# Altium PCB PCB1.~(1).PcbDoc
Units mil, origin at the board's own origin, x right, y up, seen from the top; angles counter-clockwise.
Board outline 2756 x 2756 mil, 4 copper layers (Top Layer, Internal Plane 1, Internal Plane 2, Bottom Layer), stack 18.2 mil thick; 14 components, 0 nets, 59 pads, 0 vias.
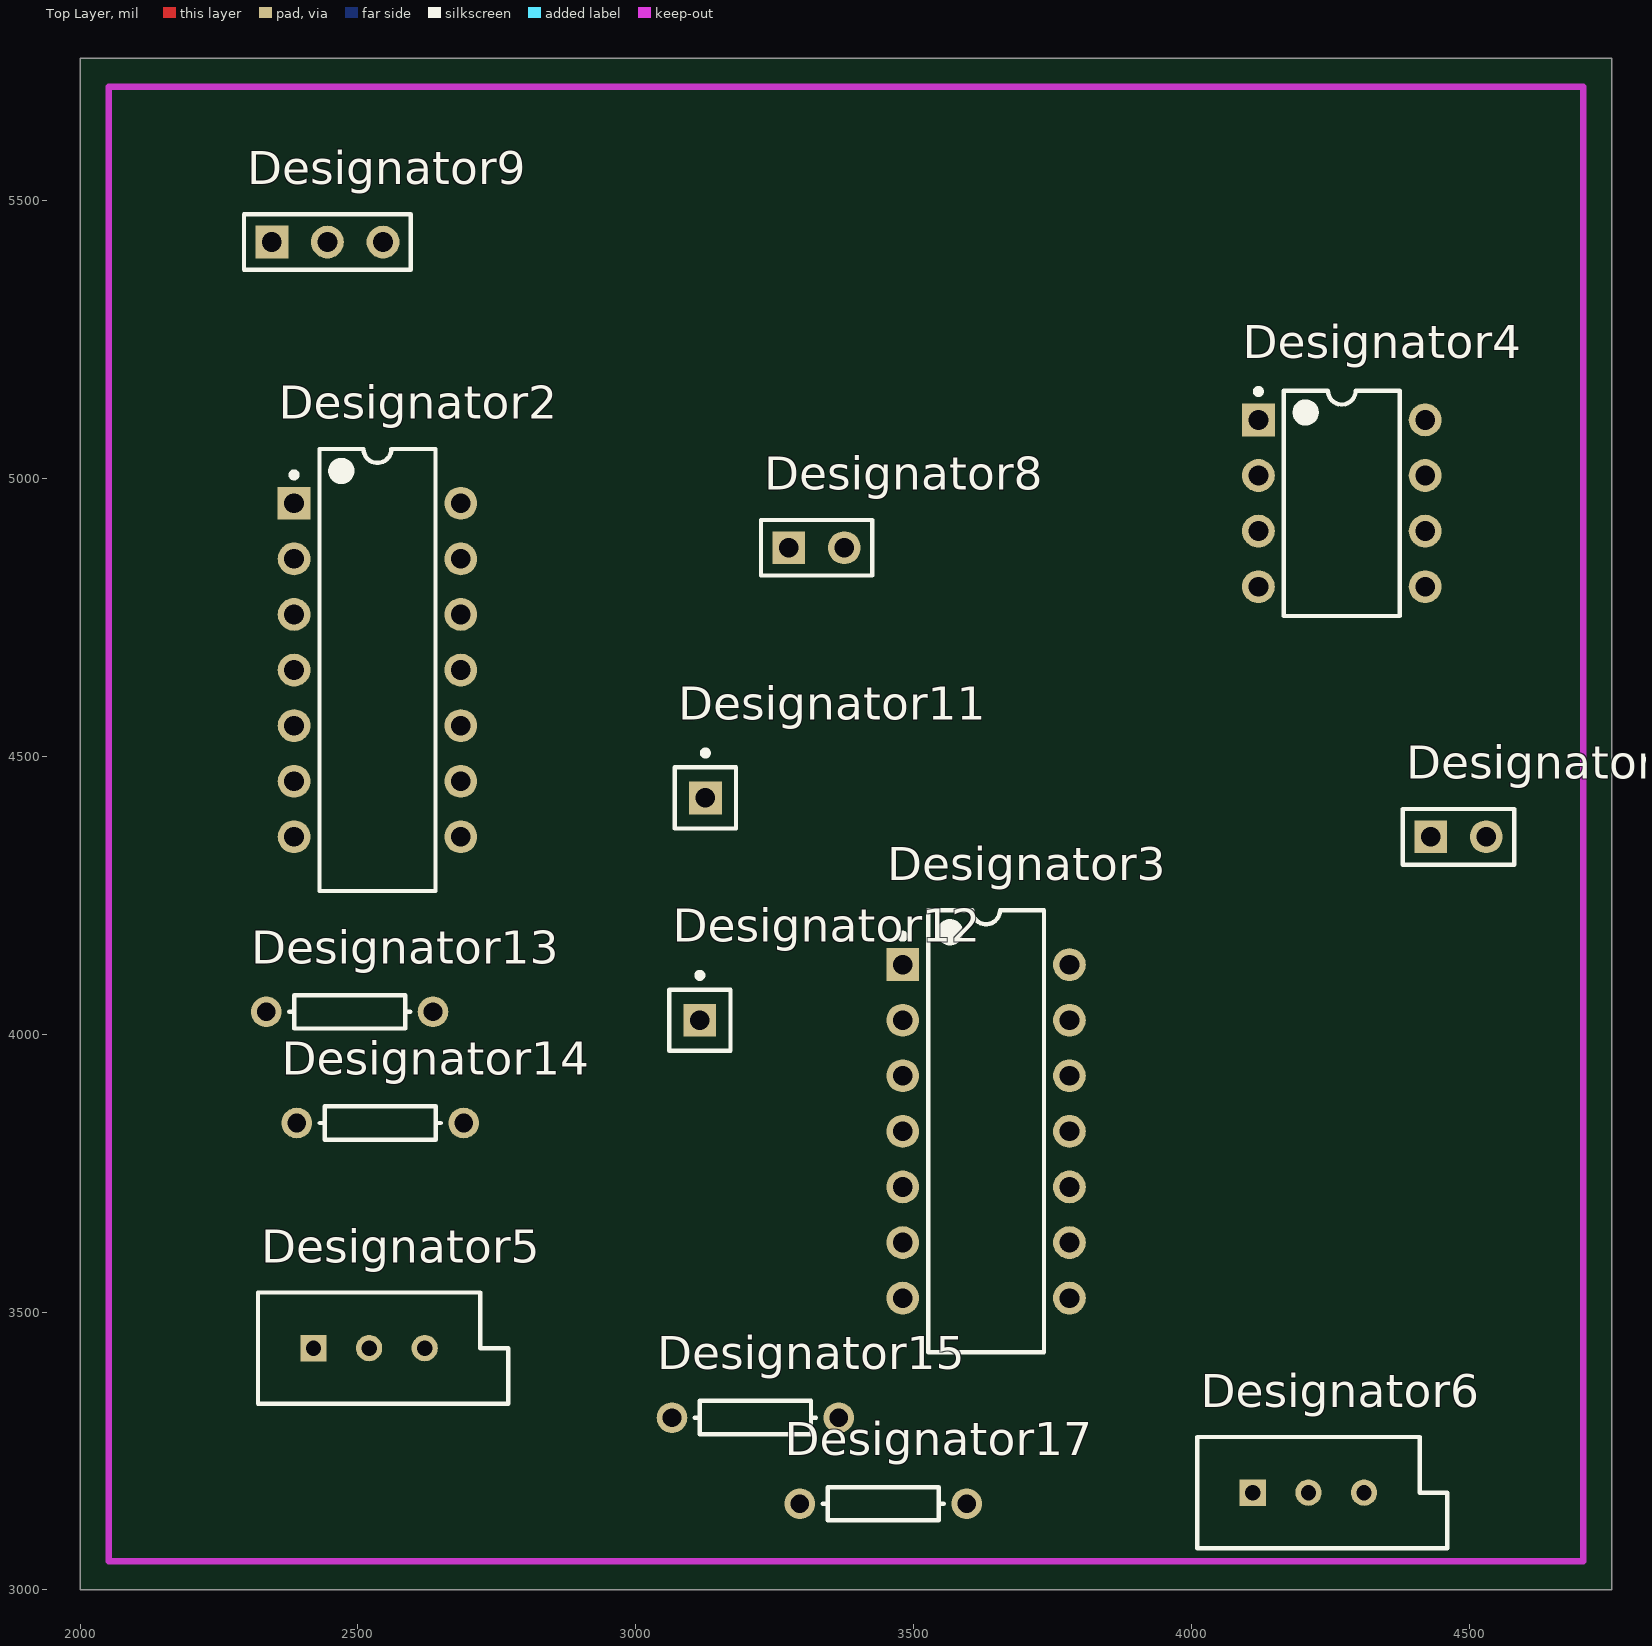
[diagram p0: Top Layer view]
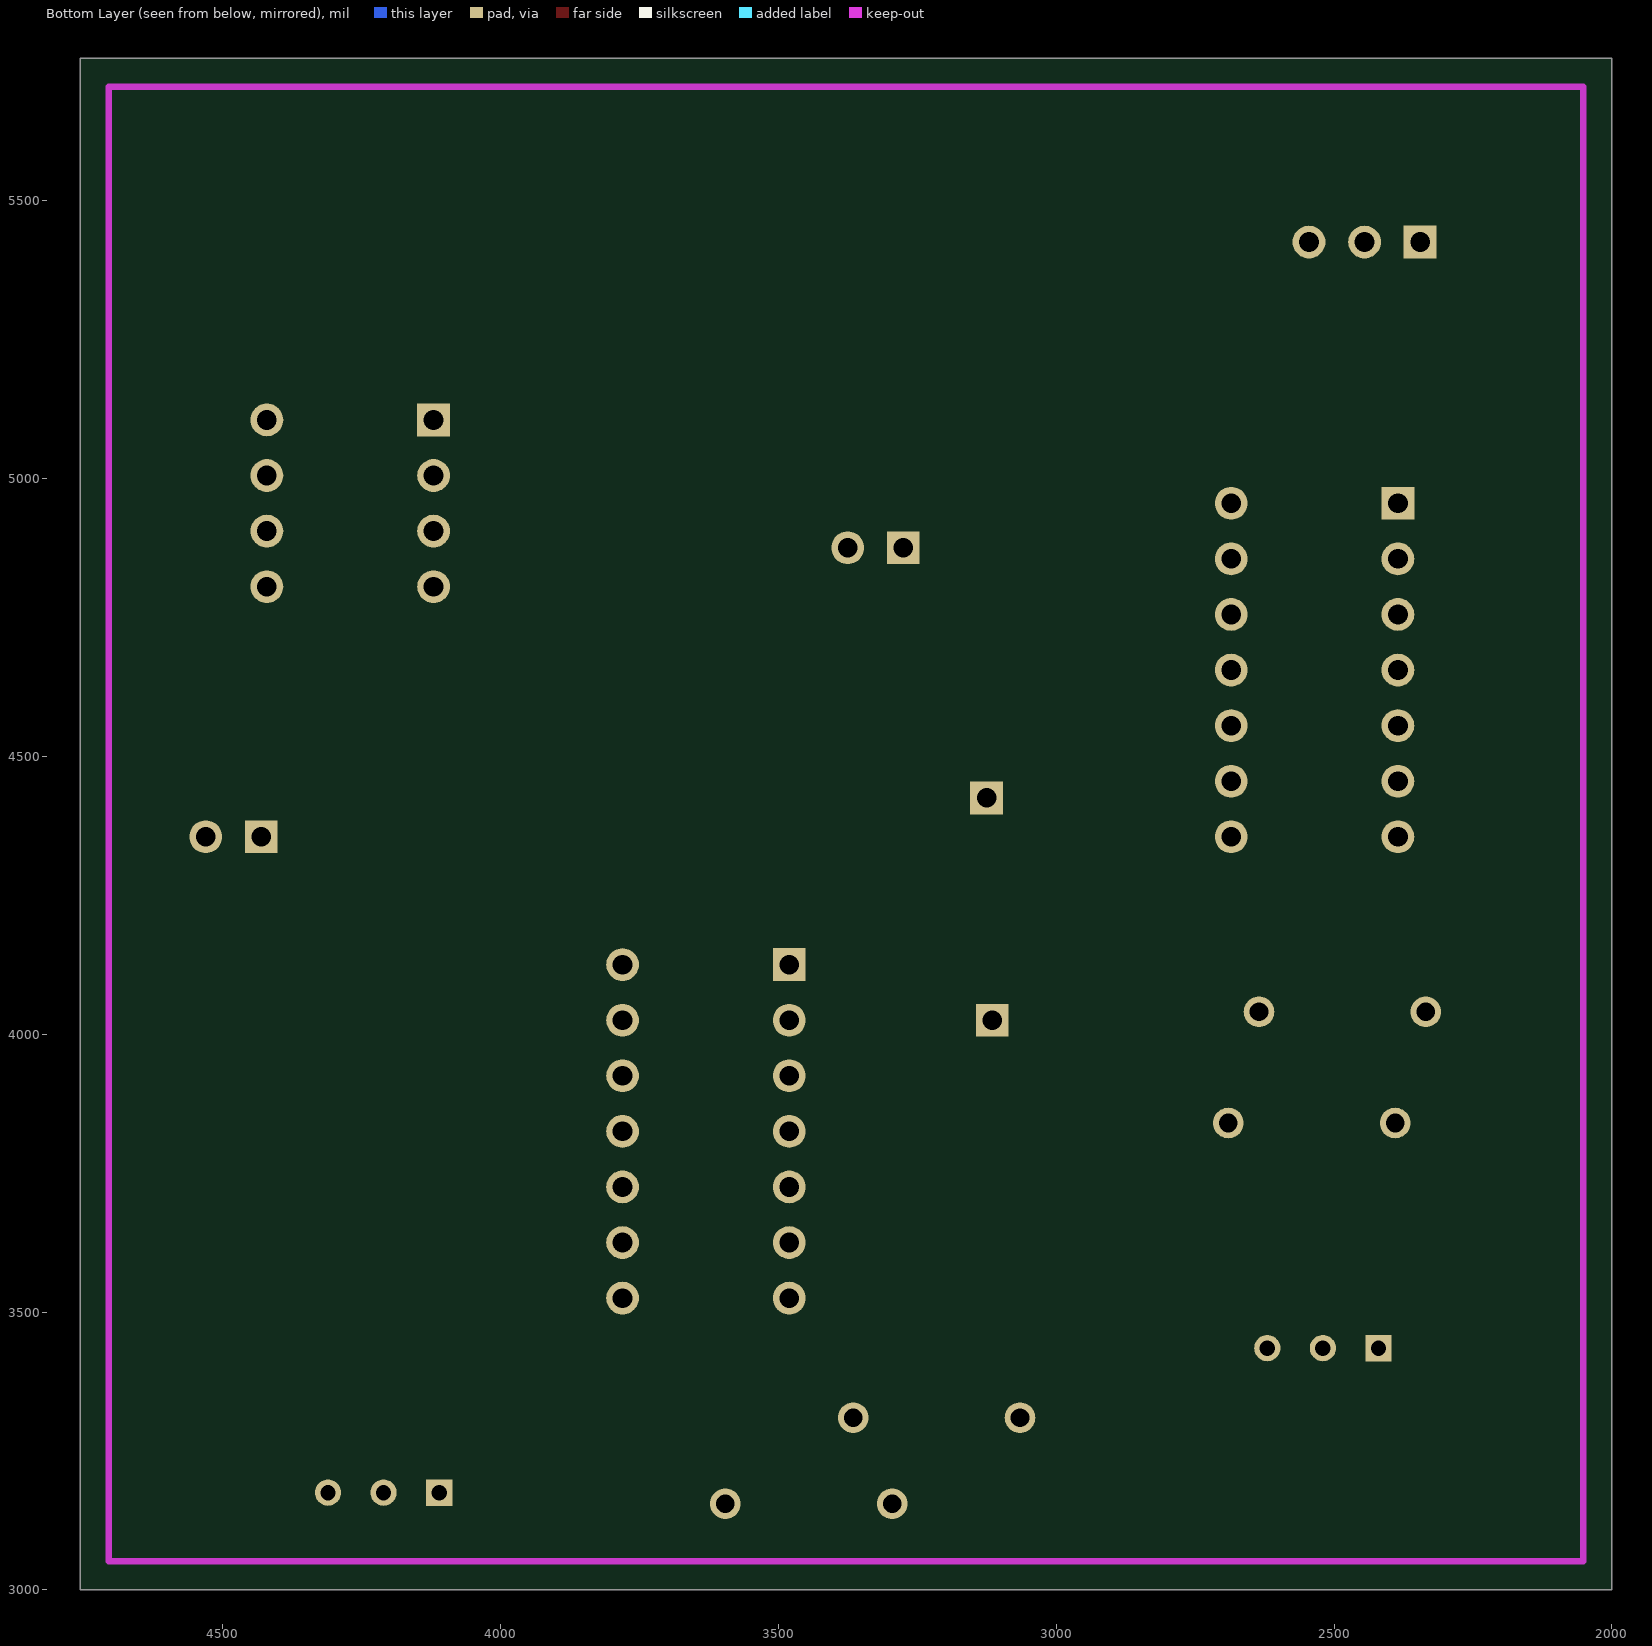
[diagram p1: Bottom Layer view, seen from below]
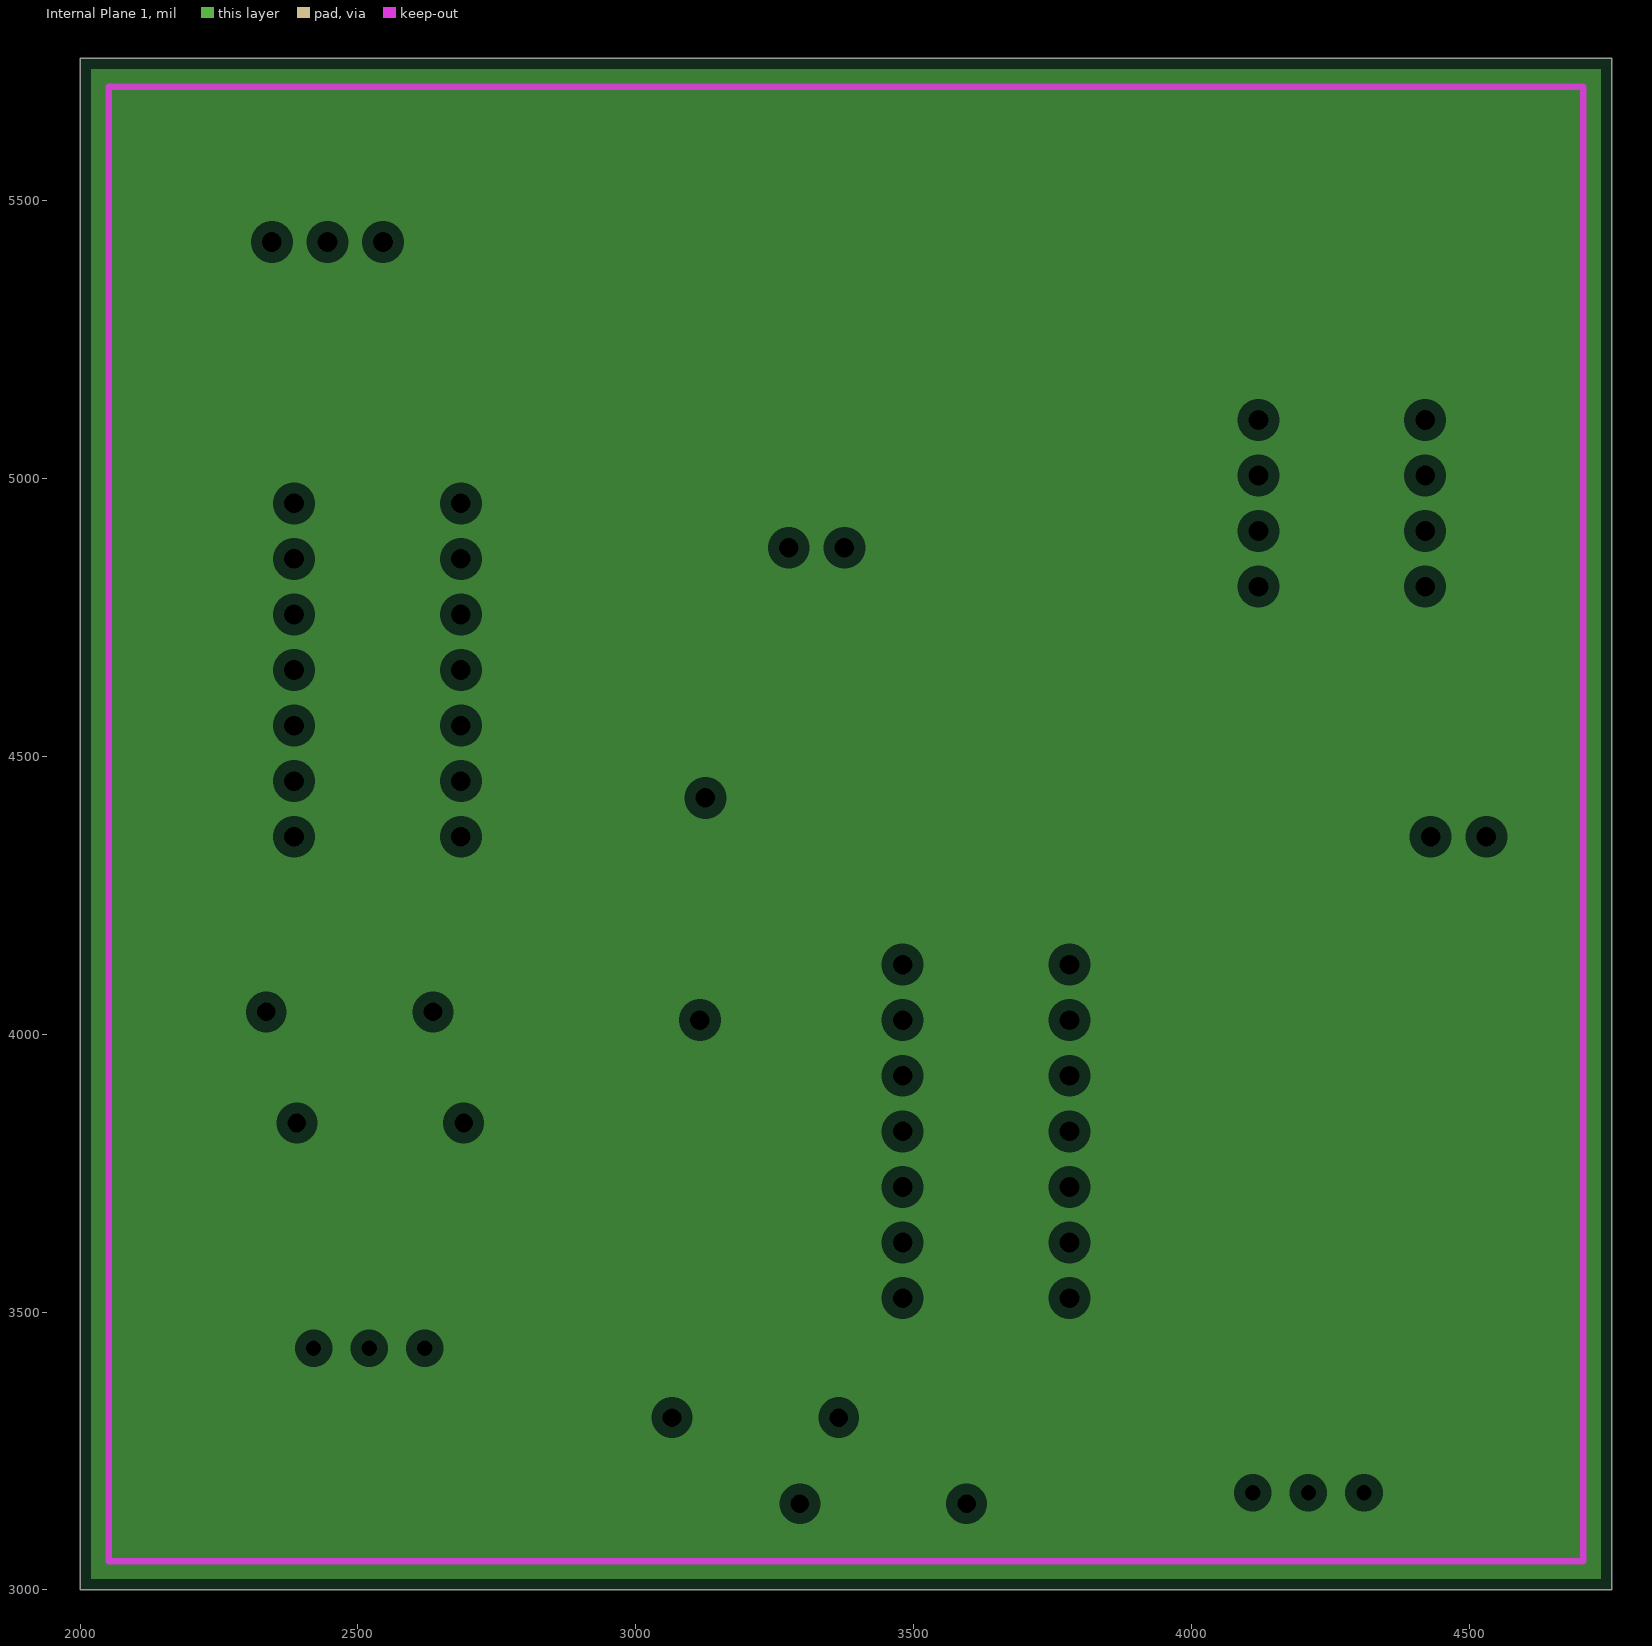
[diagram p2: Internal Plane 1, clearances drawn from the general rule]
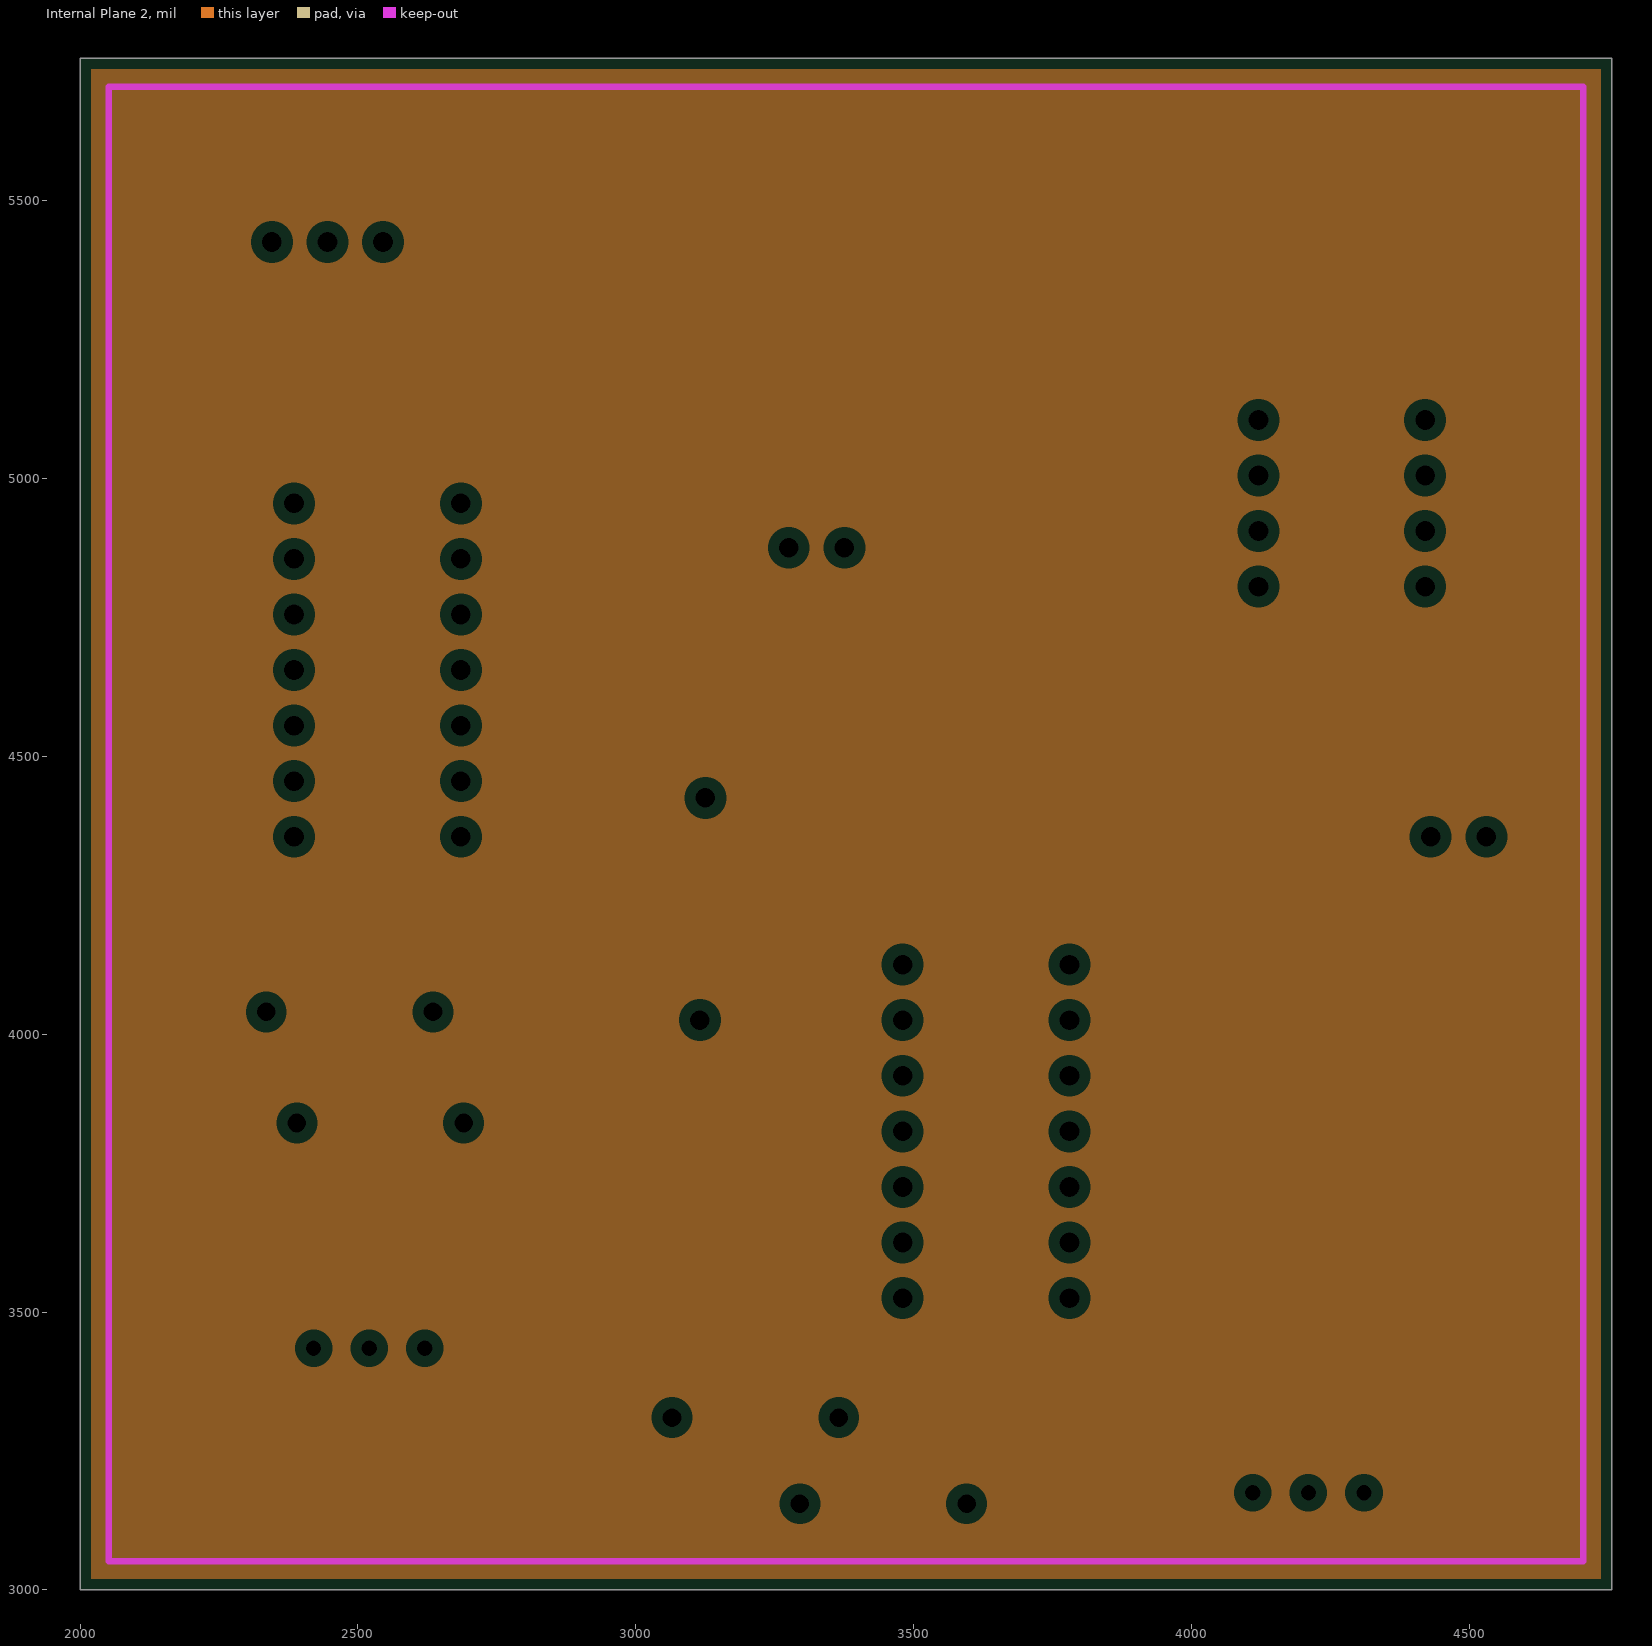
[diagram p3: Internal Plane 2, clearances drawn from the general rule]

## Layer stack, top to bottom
Top Solder: solder mask 0.4, Solder Resist, Dk 3.5
Top Layer: signal copper 1.4
Internal Plane 1: plane copper 1.4
Internal Plane 2: plane copper 1.4
Dielectric 1: dielectric 12.6, FR-4, Dk 4.8
Bottom Layer: signal copper 1.4
Bottom Solder: solder mask 0.4, Solder Resist, Dk 3.5

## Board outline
2000,3000 4756,3000 4756,5756 2000,5756

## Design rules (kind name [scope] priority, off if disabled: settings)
Clearance [All] p1: gap=30
PlaneClearance [All] p1: clearance=20
PlaneConnect [All] p1: planeconnectstyle=Relief reliefexpansion=20 reliefentries=4 reliefconductorwidth=10 reliefairgap=10
PolygonConnect [All] p1: connectstyle=Relief reliefconductorwidth=10 reliefentries=4 polygonreliefangle="90 Angle" airgapwidth=10
RoutingVias [All] p1: holewidth=32 width=62 viastyle="Through Hole" minholewidth=28 minwidth=50 maxholewidth=28 maxwidth=50
SolderMaskExpansion [All] p1: expansion=4
Width [All] p1: maxlimit=20 minlimit=20 preferedwidth=20
28 further rules are at their usual default settings.

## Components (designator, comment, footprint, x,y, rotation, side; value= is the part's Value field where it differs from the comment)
Designator2 "Comment" DIP-14 2535,4655 r0 top
Designator3 "Comment" DIP-14 3630,3825 r0 top
Designator4 "Comment" DIP-8 4270,4955 r0 top
Designator5 "Comment" VR5 2520,3435 r0 top
Designator6 "Comment" VR5 4210,3175 r0 top
Designator7 "Comment" HDR1X2 4430,4355 r0 top
Designator8 "Comment" HDR1X2 3275,4875 r0 top
Designator9 "Comment" HDR1X3 2345,5425 r0 top
Designator11 "Comment" PIN1 3125,4425 r0 top
Designator12 "Comment" PIN1 3115,4025 r0 top
Designator13 "Comment" AXIAL-0.3 2485,4040 r0 top
Designator14 "Comment" AXIAL-0.3 2540,3840 r0 top
Designator15 "Comment" AXIAL-0.3 3215,3310 r0 top
Designator17 "Comment" AXIAL-0.3 3445,3155 r0 top

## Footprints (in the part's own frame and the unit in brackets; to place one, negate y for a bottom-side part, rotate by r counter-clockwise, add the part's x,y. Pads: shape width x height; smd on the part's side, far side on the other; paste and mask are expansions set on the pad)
AXIAL-0.3 [mm] "Axial Device, Thru-Hole; 2 Leads; 0.3 in Pin Spacing"
  round 1.4 hole 0.85: 1(-3.81,0) 2(3.81,0)
  silkscreen extent -2.77,-0.76 2.77,0.76
DIP-8 [mm] "DIP; 8 Leads; Row Spacing 7.62 mm; Pitch 2.54 mm"
  rect 1.5x1.5 hole 0.9: 1(-3.81,3.81)
  round 1.5 hole 0.9: 2(-3.81,1.27) 3(-3.81,-1.27) 4(-3.81,-3.81) 5(3.81,-3.81) 6(3.81,-1.27) 7(3.81,1.27) 8(3.81,3.81)
  silkscreen extent -3.93,-5.15 2.65,5.23, body extent -3.6,-5.15 3.6,5.15, height 5.08
DIP-14 [mm] "DIP; 14 Leads; Row Spacing 7.62 mm; Pitch 2.54 mm"
  rect 1.5x1.5 hole 0.9: 1(-3.81,7.62)
  round 1.5 hole 0.9: 2(-3.81,5.08) 3(-3.81,2.54) 4(-3.81,0) 5(-3.81,-2.54) 6(-3.81,-5.08) 7(-3.81,-7.62) 8(3.81,-7.62) 9(3.81,-5.08) 10(3.81,-2.54) 11(3.81,0) 12(3.81,2.54) 13(3.81,5.08) 14(3.81,7.62)
  silkscreen extent -3.93,-10.1 2.65,10.1, body extent -3.6,-10.1 3.6,10.1, height 5.08
HDR1X2 [mm] "Connector; Header; 2 Position"
  rect 1.5x1.5 hole 0.9: 1(0,0)
  round 1.5 hole 0.9: 2(2.54,0)
  silkscreen extent -1.27,-1.27 3.81,1.27
HDR1X3 [mm] "Connector; Header; 3 Position"
  rect 1.5x1.5 hole 0.9: 1(0,0)
  round 1.5 hole 0.9: 2(2.54,0) 3(5.08,0)
  silkscreen extent -1.27,-1.27 6.35,1.27
PIN1 [mm] "Generic Antenna; 1 Lead"
  rect 1.5x1.5 hole 0.9: 1(0,0)
  silkscreen extent -1.4,-1.4 1.4,2.17
VR5 [mm] "Thru-Hole; 3 Leads"
  rect 1.2x1.2 hole 0.7: 1(-2.54,0)
  round 1.2 hole 0.7: 2(0,0) 3(2.54,0)
  silkscreen extent -5.08,-2.54 6.35,2.54

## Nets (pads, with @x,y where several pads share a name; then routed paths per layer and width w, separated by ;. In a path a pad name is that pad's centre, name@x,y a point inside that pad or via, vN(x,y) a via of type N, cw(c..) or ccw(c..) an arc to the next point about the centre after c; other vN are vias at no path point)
pads on no net: Designator2.1 Designator2.2 Designator2.3 Designator2.4 Designator2.5 Designator2.6 Designator2.7 Designator2.8 Designator2.9 Designator2.10 Designator2.11 Designator2.12 Designator2.13 Designator2.14 Designator3.1 Designator3.2 Designator3.3 Designator3.4 Designator3.5 Designator3.6 Designator3.7 Designator3.8 Designator3.9 Designator3.10 Designator3.11 Designator3.12 Designator3.13 Designator3.14 Designator4.1 Designator4.2 Designator4.3 Designator4.4 Designator4.5 Designator4.6 Designator4.7 Designator4.8 Designator5.1 Designator5.2 Designator5.3 Designator6.1 Designator6.2 Designator6.3 Designator7.1 Designator7.2 Designator8.1 Designator8.2 Designator9.1 Designator9.2 Designator9.3 Designator11.1 Designator12.1 Designator13.1 Designator13.2 Designator14.1 Designator14.2 Designator15.1 Designator15.2 Designator17.1 Designator17.2

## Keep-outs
Keep-Out Layer:
  lines w11.81: 2051.18,3051.18 4704.82,3051.18 4704.82,5704.82 2051.18,5704.82 2051.18,3051.18

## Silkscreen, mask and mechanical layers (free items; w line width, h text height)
Drill Drawing:
  text ".LEGEND" at 4956,3200 h60
  text "Drill Drawing." at 4956,3100 h60

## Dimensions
2051.18,3051.18 to 4704.82,3051.18 on Mechanical 1
2051.18,3051.18 to 2051.18,5704.82 on Mechanical 1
